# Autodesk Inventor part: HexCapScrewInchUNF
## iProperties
Author: Administrator
Shininess: 86.0
PropertySet Name: _Private Model Information
Created: 2000-12
Part Number: HexCapScrewInchUNF
Document SubType Name: Modeling
Designer: Administrator
Control State: 0
Master: False
Checked Out: False
PropertySet Name: Design Tracking Control
Density: 0.0
Volumn: 0.0
Area: 0.0
PropertySet Name: Model Information
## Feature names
1. Extrusion1
2. Extrusion2
3. Revolution1
4. Extrusion3
5. Chamfer1
